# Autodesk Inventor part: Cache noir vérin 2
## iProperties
Shininess: 20.0
Angle Display Precision: 2
Document Length Units: 11269
Document Angle Units: 11279
Document Time Units: 11290
Document Mass Units: 11283
Document Length Units Precision: 3
Document Angle Units Precision: 2
Compacted: True
Created: 2002-09
Part Number: Cache noir vérin 2
Material: Par défaut
Document SubType Name: Modélisation
Designer: administrateur
Density: 0.0
Volumn: 0.0
Area: 0.0
PropertySet Name: Model Information
Control State: 0
Master: False
Checked Out: False
Author: administrateur
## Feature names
1. Extrusion1
2. Chanfrein1 [Chamfer]
3. Chanfrein2 [Chamfer]
4. Chanfrein3 [Chamfer]
5. Chanfrein4 [Chamfer]
6. Congé1 [Fillet]
7. Congé2 [Fillet]
8. Extrusion2
9. Chanfrein5 [Chamfer]
10. Chanfrein6 [Chamfer]
11. Chanfrein7 [Chamfer]
12. Chanfrein8 [Chamfer]
13. Extrusion3
